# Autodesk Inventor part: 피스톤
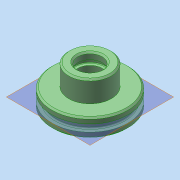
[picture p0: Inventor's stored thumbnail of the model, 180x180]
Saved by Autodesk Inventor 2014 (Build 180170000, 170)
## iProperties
Created: 2023-03
Part Number: 피스톤
Material: 강철, 연강
Document SubType Name: Modeling
Designer: mdu-01
Density: 1 g/cm^3
Appearance: 기본값(1)
Author: mdu-01
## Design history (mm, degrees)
sketch "스케치1"
  geometry: L1 (0, 0)-(13, 0); L2 (14, 1)-(14, 6); L3 (14, 6)-(24, 6); L4 (25, 7)-(25, 9.65); L5 (25, 9.65)-(22.8, 9.65); L6 (22, 10.45)-(22, 13.55); L7 (22.8, 14.35)-(25, 14.35); L8 (25, 14.35)-(25, 17); L9 (24, 18)-(14, 18); L10 (14, 18)-(14, 31); L11 (13, 32)-(9, 32); L12 (8, 20)-(0, 20); L13 (0, 20)-(0, 0); L14 (22, 12)-(25, 12); L15 (9, 32)-(8, 31); L16 (14, 31)-(13, 32); L17 (25, 17)-(24, 18); L18 (24, 6)-(25, 7); L19 (13, 0)-(14, 1); L20 (8, 27.6)-(9.6, 27.6); L21 (10, 27.2)-(10, 24.8); L22 (9.6, 24.4)-(8, 24.4); L23 (8, 31)-(8, 27.6); L24 (8, 24.4)-(8, 20); A1 r 0.8 centre (22.8, 10.45) between (22, 10.45) and (22.8, 9.65); A2 r 0.8 centre (22.8, 13.55) between (22.8, 14.35) and (22, 13.55); A3 r 0.4 centre (9.6, 27.2) between (10, 27.2) and (9.6, 27.6); A4 r 0.4 centre (9.6, 24.8) between (9.6, 24.4) and (10, 24.8); 6 further points
  constraints: 48 end point, 11 parallel, 11 point on line, 8 perpendicular, 8 point on circle, 8 tangent, 4 centre point, 3 collinear, 2 equal radius, 2 midpoint, 1 horizontal, 1 other
  dimensions: "d0" = 50 diameter of L4 L13; "d2" = 0.8 radius of A1; "d3" = 32 distance between parallel lines of L11 L1; "d4" = 14 distance between parallel lines of L9 L11; "d5" = 4.7 distance between parallel lines of L5 L7; "d6" = 6 distance between parallel lines of L3 L1; "d7" = 44 diameter of L6 L13; "d8" = 28 diameter of L2 L13; "d10" = 12 distance between parallel lines of L12 L11; "d11" = 1 distance of L11.end point (8, 32); "d12" = 1 distance of L15.end point (8, 32) (= d11); "d13" = 1 distance of L10.end point (14, 32) (= d11); "d14" = 1 distance of L11.start point (14, 32) (= d13); "d15" = 1 distance of L8.end point (25, 18) (= d11); "d16" = 1 distance of L9.start point (25, 18) (= d15); "d17" = 1 distance of L3.end point (25, 6) (= d11); "d18" = 1 distance of L4.start point (25, 6) (= d17); "d19" = 1 distance of L1.end point (14, 0) (= d11); "d20" = 1 distance of L2.start point (14, 0) (= d19); "d31" = 16 diameter of L23 L13; "d32" = 0.4 radius of A3; "d33" = 6 distance from line of point (10, 26) L11; "d34" = 3.2 distance between parallel lines of L22 L20; "d35" = 20 diameter of L21 L13
revolve "회전1" sketch "스케치1" stored, may be unused: angle "d21" = 90 deg
hole "구멍1" diameter "d24" = 9; stored, may be unused: countersink angle "d28" = 90 deg, drill point angle "d30" = 118 deg; dims "d22" = 10, "d23" = 10, "d25" = 6, "d26" = 15, "d27" = 9, "d29" = 8
node "작업 평면1"
node "작업 평면2"
node "솔리드1"
other parameters: "d9" = 16
